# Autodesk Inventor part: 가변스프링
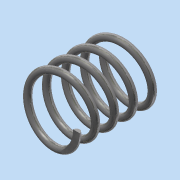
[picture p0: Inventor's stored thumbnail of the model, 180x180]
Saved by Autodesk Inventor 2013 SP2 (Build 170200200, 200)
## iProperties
Created: 2015-03
Part Number: 가변스프링
Material: 강철, 탄소
Document SubType Name: Modeling
Designer: dgall
Density: 7.87 g/cm^3
Mass: 48.1255 g
Surface Area: 62.1096 cm^2
Volume: 6.11506 cm^3
Author: dgall
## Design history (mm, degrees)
sketch "스케치1"
  geometry: L1 (0, 0)-(17.5, 0); L2 (0, 0)-(0, 51.343); L3 (0, 51.343)-(17.5, 51.343); C1 r 2 at (17.5, 0)
  constraints: 7 end point, 2 perpendicular, 1 centre point, 1 coincident, 1 horizontal, 1 vertical alignment
  dimensions: "d0" = 4 diameter of C1; "d2" = 35 diameter of L1.end L2; "d3" = 51.34254 distance of L1.start L2.end (derived)
feature "코일1" pitch "d4" = 10; turns "d6" = 4.5; dims "d5" = 51.34254 (= d3), "d7" = 0, angle "d8" = 90 deg, angle "d9" = 90 deg, "d10" = 0, "d11" = 0
sketch "스케치2"
  geometry: L1 (58.337, -19.673)-(51.343, -19.673); L2 (51.343, -19.673)-(51.343, 10.68); L3 (51.343, 10.68)-(58.337, 10.68); L4 (58.337, 10.68)-(58.337, -19.673); L5 (0, -37.787)-(-36.411, -37.787); L6 (-36.411, -37.787)-(-36.411, 58.096); L7 (-36.411, 58.096)-(0, 58.096); L8 (0, 58.096)-(0, -37.787); 2 further points
  constraints: 16 end point, 4 parallel, 2 horizontal, 2 perpendicular, 2 point on line, 1 horizontal alignment
extrude "돌출1" cut sketch "스케치2" stored distance "d12" = 0; taper "d13" = 0 deg
node "솔리드1"
